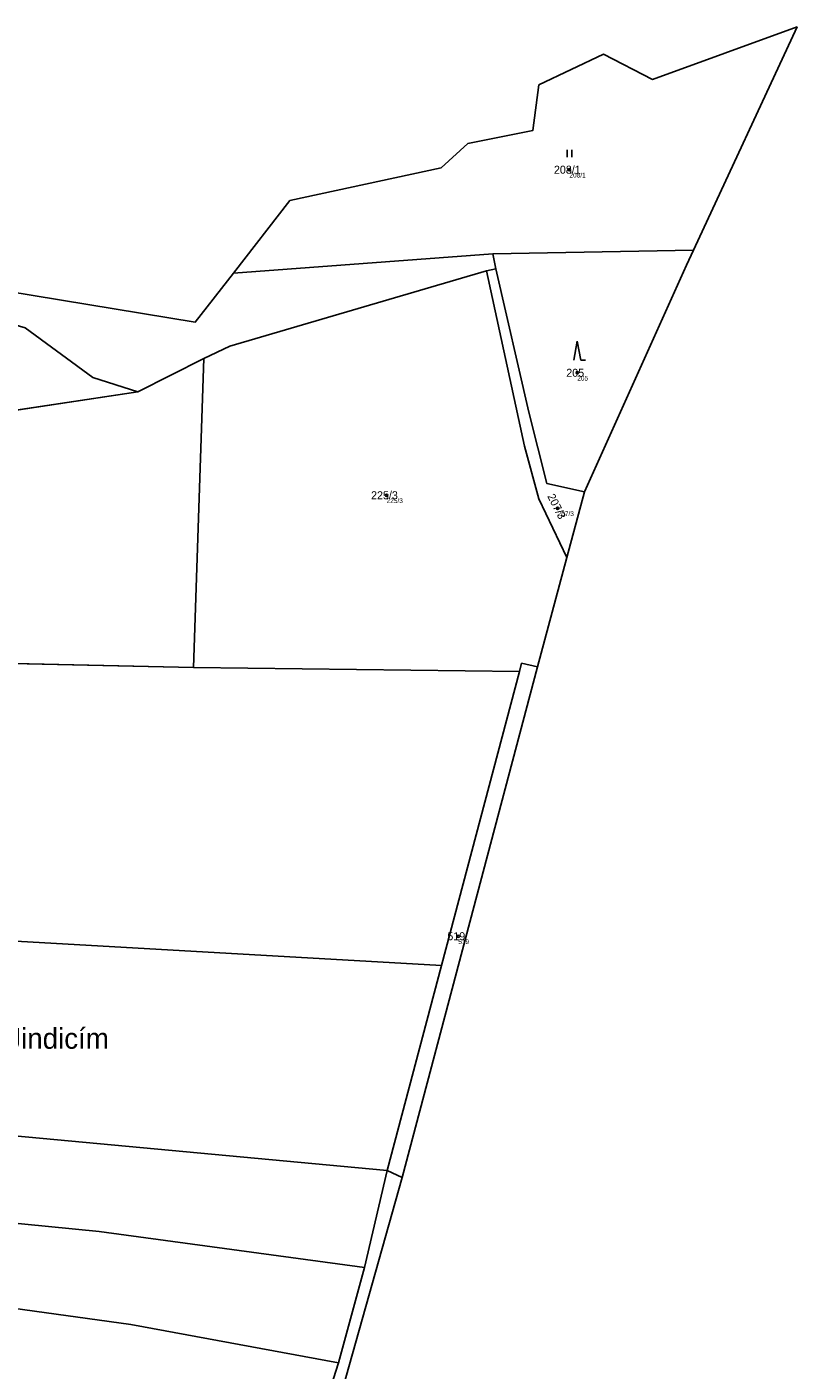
# Model space of a CAD drawing. Extents: x -700238 to -698499, y -1070626 to -1068006.
# Drawn here: x -699200.2 to -699036.5, y -1068910.8 to -1068625.5 of the extents above; entities that cross this region are included whole.
import ezdxf

# ---------------------------------------------------------------- set-up
doc = ezdxf.new("R2010")
doc.units = 0
for name, color, linetype in [('Definiční body', 7, 'Continuous'), ('Hranice parcel', 7, 'Continuous'), ('Parcelní čísla', 7, 'Continuous'), ('Polygon ku', 7, 'Continuous'), ('Polygon parcely', 7, 'Continuous'), ('Pop  PČ popisy', 7, 'Continuous'), ('Značky kultur', 7, 'Continuous')]:
    doc.layers.add(name, color=color, linetype=linetype)

msp = doc.modelspace()

# ---------------------------------------------------------------- linework, layer by layer
at = {"layer": 'Definiční body'}
for centre in [(-699084.9, -1068655.86994), (-699083.25, -1068698.99994), (-699123.76, -1068725.00994), (-699087.41, -1068727.76994), (-699108.52, -1068818.66994)]:
    msp.add_circle(centre, 0.25, dxfattribs=at)
at = {"layer": 'Hranice parcel'}
for p, q in [((-699036.51, -1068625.53), (-699058.54, -1068672.96)), ((-699156.31, -1068677.82), (-699144.3, -1068662.43)), ((-699156.31, -1068677.82), (-699101.17, -1068673.72)), ((-699058.54, -1068672.96), (-699101.17, -1068673.72)), ((-699101.17, -1068673.72), (-699100.57, -1068676.95)), ((-699058.54, -1068672.96), (-699060.01, -1068676.13)), ((-699060.01, -1068676.13), (-699081.71, -1068724.32)), ((-699164.43, -1068688.22), (-699156.31, -1068677.82)), ((-699100.57, -1068676.95), (-699102.52, -1068677.35)), ((-699176.6, -1068703.08), (-699162.58, -1068695.94)), ((-699164.78, -1068761.6), (-699162.58, -1068695.94)), ((-699176.6, -1068703.08), (-699230.46, -1068711.14)), ((-699081.71, -1068724.32), (-699085.44, -1068738.22)), ((-699085.44, -1068738.22), (-699091.67, -1068761.47)), ((-699320.54, -1068758.12), (-699164.78, -1068761.6)), ((-699095.55, -1068762.45), (-699164.78, -1068761.6)), ((-699091.67, -1068761.47), (-699120.47, -1068869.91)), ((-699095.55, -1068762.45), (-699112.1, -1068824.87)), ((-699112.1, -1068824.87), (-699123.65, -1068868.45)), ((-699128.48, -1068889.06), (-699123.65, -1068868.45)), ((-699123.65, -1068868.45), (-699120.47, -1068869.91)), ((-699133.96, -1068909.29), (-699128.48, -1068889.06)), ((-699140.02, -1068928.19), (-699133.96, -1068909.29))]:
    msp.add_line(p, q, dxfattribs=at)
for points in [[(-699144.3, -1068662.43), (-699112.18, -1068655.45), (-699106.51, -1068650.33), (-699092.7, -1068647.57), (-699091.4, -1068637.86), (-699077.67, -1068631.35), (-699067.28, -1068636.68), (-699036.51, -1068625.53)], [(-699204.82, -1068667.14), (-699204.5, -1068681.69), (-699164.43, -1068688.22)], [(-699162.58, -1068695.94), (-699157.07, -1068693.35), (-699102.52, -1068677.35)], [(-699102.52, -1068677.35), (-699094.44, -1068714.57), (-699091.39, -1068725.74), (-699085.44, -1068738.22)], [(-699100.57, -1068676.95), (-699093.51, -1068707.37), (-699089.7, -1068722.52), (-699081.71, -1068724.32)], [(-699223.88, -1068693.51), (-699222.92, -1068687.7), (-699212.44, -1068685.98), (-699200.59, -1068689.47), (-699186.19, -1068700.02), (-699176.6, -1068703.08)], [(-699091.67, -1068761.47), (-699095.08, -1068760.68), (-699095.55, -1068762.45)], [(-699346.21, -1068814.3), (-699244.79, -1068817.34), (-699112.1, -1068824.87)], [(-699340.34, -1068849.53), (-699298.11, -1068852.24), (-699123.65, -1068868.45)], [(-699343.95, -1068864.6), (-699238.04, -1068876.16), (-699184.84, -1068881.42), (-699128.48, -1068889.06)], [(-699120.47, -1068869.91), (-699133.87, -1068917.39), (-699135.17, -1068921.35)], [(-699345.65, -1068879.11), (-699223.74, -1068894.86), (-699178.12, -1068901.11), (-699133.96, -1068909.29)]]:
    msp.add_lwpolyline(points, dxfattribs=at)
at = {"layer": 'Polygon ku'}
for points in [[(-699081.71, -1068724.32), (-699060.01, -1068676.13), (-699058.54, -1068672.96), (-699036.51, -1068625.53), (-699067.28, -1068636.68), (-699077.67, -1068631.35), (-699091.4, -1068637.86), (-699092.7, -1068647.57), (-699106.51, -1068650.33), (-699112.18, -1068655.45), (-699144.3, -1068662.43), (-699156.31, -1068677.82), (-699164.43, -1068688.22), (-699204.5, -1068681.69)], [(-699133.87, -1068917.39), (-699120.47, -1068869.91), (-699091.67, -1068761.47), (-699085.44, -1068738.22), (-699081.71, -1068724.32)]]:
    msp.add_lwpolyline(points, dxfattribs=at)
at = {"layer": 'Polygon parcely'}
for points in [[(-699101.17, -1068673.72), (-699058.54, -1068672.96), (-699036.51, -1068625.53), (-699067.28, -1068636.68), (-699077.67, -1068631.35), (-699091.4, -1068637.86), (-699092.7, -1068647.57), (-699106.51, -1068650.33), (-699112.18, -1068655.45), (-699144.3, -1068662.43), (-699156.31, -1068677.82)], [(-699081.71, -1068724.32), (-699060.01, -1068676.13), (-699058.54, -1068672.96), (-699101.17, -1068673.72), (-699100.57, -1068676.95), (-699093.51, -1068707.37), (-699089.7, -1068722.52)], [(-699085.44, -1068738.22), (-699091.39, -1068725.74), (-699094.44, -1068714.57), (-699102.52, -1068677.35), (-699157.07, -1068693.35), (-699162.58, -1068695.94), (-699164.78, -1068761.6), (-699095.55, -1068762.45), (-699095.08, -1068760.68), (-699091.67, -1068761.47)], [(-699081.71, -1068724.32), (-699089.7, -1068722.52), (-699093.51, -1068707.37), (-699100.57, -1068676.95), (-699102.52, -1068677.35), (-699094.44, -1068714.57), (-699091.39, -1068725.74), (-699085.44, -1068738.22)], [(-699230.46, -1068711.14), (-699176.6, -1068703.08), (-699186.19, -1068700.02), (-699200.59, -1068689.47), (-699212.44, -1068685.98), (-699222.92, -1068687.7), (-699223.88, -1068693.51), (-699225.05, -1068701.48)], [(-699320.54, -1068758.12), (-699164.78, -1068761.6), (-699162.58, -1068695.94), (-699176.6, -1068703.08), (-699230.46, -1068711.14), (-699255.75, -1068720.08), (-699278.5, -1068722.49), (-699302, -1068731.73)], [(-699346.21, -1068814.3), (-699244.79, -1068817.34), (-699112.1, -1068824.87), (-699095.55, -1068762.45), (-699164.78, -1068761.6), (-699320.54, -1068758.12), (-699332.59, -1068768.07), (-699343.01, -1068797.58)], [(-699112.1, -1068824.87), (-699123.65, -1068868.45), (-699120.47, -1068869.91), (-699091.67, -1068761.47), (-699095.08, -1068760.68), (-699095.55, -1068762.45)], [(-699340.34, -1068849.53), (-699298.11, -1068852.24), (-699123.65, -1068868.45), (-699112.1, -1068824.87), (-699244.79, -1068817.34), (-699346.21, -1068814.3)], [(-699238.04, -1068876.16), (-699184.84, -1068881.42), (-699128.48, -1068889.06), (-699123.65, -1068868.45), (-699298.11, -1068852.24), (-699340.34, -1068849.53), (-699343.95, -1068864.6)], [(-699223.74, -1068894.86), (-699178.12, -1068901.11), (-699133.96, -1068909.29), (-699128.48, -1068889.06), (-699184.84, -1068881.42), (-699238.04, -1068876.16), (-699343.95, -1068864.6), (-699345.65, -1068879.11)], [(-699133.96, -1068909.29), (-699178.12, -1068901.11), (-699223.74, -1068894.86), (-699345.65, -1068879.11), (-699347.13, -1068893.81), (-699242.99, -1068910.5), (-699140.02, -1068928.19)]]:
    msp.add_lwpolyline(points, close=True, dxfattribs=at)
for points in [[(-699200.59, -1068689.47), (-699186.19, -1068700.02), (-699176.6, -1068703.08), (-699162.58, -1068695.94), (-699157.07, -1068693.35), (-699102.52, -1068677.35), (-699100.57, -1068676.95), (-699101.17, -1068673.72), (-699156.31, -1068677.82), (-699164.43, -1068688.22), (-699204.5, -1068681.69)], [(-699133.87, -1068917.39), (-699120.47, -1068869.91), (-699123.65, -1068868.45), (-699128.48, -1068889.06), (-699133.96, -1068909.29), (-699140.02, -1068928.19)]]:
    msp.add_lwpolyline(points, dxfattribs=at)
at = {"layer": 'Značky kultur'}
for p, q in [((-699085.411, -1068653.17), (-699085.411, -1068651.67)), ((-699084.41, -1068653.17), (-699084.41, -1068651.67)), ((-699083.25, -1068692.3), (-699084, -1068696.3)), ((-699082.5, -1068696.3), (-699083.25, -1068692.3)), ((-699082.5, -1068696.3), (-699081.504, -1068696.3))]:
    msp.add_line(p, q, dxfattribs=at)

# ---------------------------------------------------------------- texts
at = {"layer": 'Definiční body'}
for s, p in [('208/1', (-699084.9, -1068657.526)), ('205', (-699083.25, -1068700.656)), ('225/3', (-699123.76, -1068726.666)), ('207/3', (-699087.41, -1068729.426)), ('519', (-699108.52, -1068820.326))]:
    msp.add_text(s, height=0.999996, dxfattribs=at).set_placement(p)
at = {"layer": 'Parcelní čísla'}
for s, p in [('208/1', (-699088.198, -1068656.72)), ('205', (-699085.575, -1068699.85)), ('225/3', (-699127.058, -1068725.86)), ('519', (-699110.845, -1068819.519))]:
    msp.add_text(s, height=1.699998, dxfattribs=at).set_placement(p)
msp.add_text('207/3', height=1.699998, rotation=297, dxfattribs=at).set_placement((-699089.664, -1068725.216))
at = {"layer": 'Pop  PČ popisy'}
msp.add_text('K Jindicím', height=4.399998, dxfattribs=at).set_placement((-699209.93, -1068842.579))

doc.saveas('drawing.dxf')
